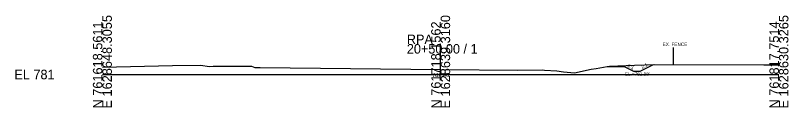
# Model space of a CAD drawing. Extents: x -26 to 203, y 990 to 7517.
# Drawn here: x -25.7 to 202.8, y 4990.3 to 5017.3 of the extents above; entities that cross this region are included whole.
import ezdxf

# ---------------------------------------------------------------- set-up
doc = ezdxf.new("R2010")
doc.units = 0
for name, color, linetype in [('Exist Cross Section Cell', 7, 'Continuous'), ('Exist XS Center Line Elevation Label', 7, 'Continuous'), ('Exist XS Ground Line', 7, 'Continuous'), ('Prop XS DDE', 7, 'Continuous'), ('Prop XS DDE Elevations', 7, 'Continuous'), ('Prop XS Side Slope Text', 7, 'Continuous')]:
    doc.layers.add(name, color=color, linetype=linetype)

msp = doc.modelspace()

# ---------------------------------------------------------------- linework, layer by layer
at = {"layer": 'Exist Cross Section Cell'}
for p, q in [((100, 5000), (100, 5008.95)), ((0, 5000), (100, 5000)), ((100, 5000), (200, 5000))]:
    msp.add_line(p, q, dxfattribs=at)
at = {"layer": 'Exist XS Ground Line'}
for p, q in [((168.79, 5002.96), (168.79, 5007.96)), ((0, 5002.2), (20.76, 5002.68)), ((20.76, 5002.68), (29.04, 5002.7)), ((29.04, 5002.7), (31.66, 5002.33)), ((149.95, 5002.43), (157.26, 5002.76)), ((157.26, 5002.76), (163.29, 5002.98)), ((163.29, 5002.98), (195.49, 5002.85)), ((195.49, 5002.85), (198.99, 5002.84)), ((198.99, 5002.84), (200, 5002.84)), ((31.66, 5002.33), (32.79, 5002.42)), ((32.79, 5002.42), (38.95, 5002.45)), ((38.95, 5002.45), (44.07, 5002.42)), ((44.07, 5002.42), (45.09, 5002.02)), ((45.09, 5002.02), (46.68, 5002.1)), ((46.68, 5002.1), (100.03, 5001.46)), ((100.03, 5001.46), (122.8, 5001.27)), ((122.8, 5001.27), (130.04, 5001.33)), ((130.04, 5001.33), (130.73, 5001.28)), ((130.73, 5001.28), (134.33, 5001.03)), ((134.33, 5001.03), (136.36, 5000.79)), ((136.36, 5000.79), (139.61, 5000.52)), ((139.61, 5000.52), (144.51, 5001.6)), ((144.51, 5001.6), (145.93, 5001.77)), ((145.93, 5001.77), (149.2, 5002.37)), ((149.2, 5002.37), (149.95, 5002.43))]:
    msp.add_line(p, q, dxfattribs=at)
at = {"layer": 'Prop XS DDE'}
for p, q in [((158.97, 5000.98), (162.95, 5002.97)), ((149.2, 5002.37), (154.2, 5002.37)), ((154.2, 5002.37), (156.97, 5000.98)), ((156.97, 5000.98), (158.97, 5000.98))]:
    msp.add_line(p, q, dxfattribs=at)

# ---------------------------------------------------------------- texts
at = {"layer": 'Exist Cross Section Cell'}
for s, p in [('E 1628648.3055', (2.8, 4990)), ('E 1628639.3160', (102.8, 4990)), ('E 1628630.3265', (202.8, 4990)), ('N 761618.5611', (0, 4990)), ('N 761718.1562', (100, 4990)), ('N 761817.7514', (200, 4990))]:
    msp.add_text(s, height=2.8, rotation=90, dxfattribs=at).set_placement(p)
for s, p in [('RPA', (90, 5008.95)), ('20+50.00 / 1', (90, 5006.15)), ('EL 781', (-26, 4998.6))]:
    msp.add_text(s, height=2.8, dxfattribs=at).set_placement(p)
at = {"layer": 'Exist XS Center Line Elevation Label'}
msp.add_text('782.46', height=1.2, dxfattribs=at).set_placement((97.46, 4999.26))
at = {"layer": 'Exist XS Ground Line'}
msp.add_text('EX. FENCE', height=1, dxfattribs=at).set_placement((165.63, 5008.37))
at = {"layer": 'Prop XS DDE Elevations'}
msp.add_text("EL.=781.98'", height=1, dxfattribs=at).set_placement((154.44, 4999.61))
at = {"layer": 'Prop XS Side Slope Text'}
for rotation, p in [(334.4608, (155.14, 5002.22)), (27.0452, (159.61, 5001.67))]:
    msp.add_text('2:1', height=1, rotation=rotation, dxfattribs=at).set_placement(p)

doc.saveas('drawing.dxf')
